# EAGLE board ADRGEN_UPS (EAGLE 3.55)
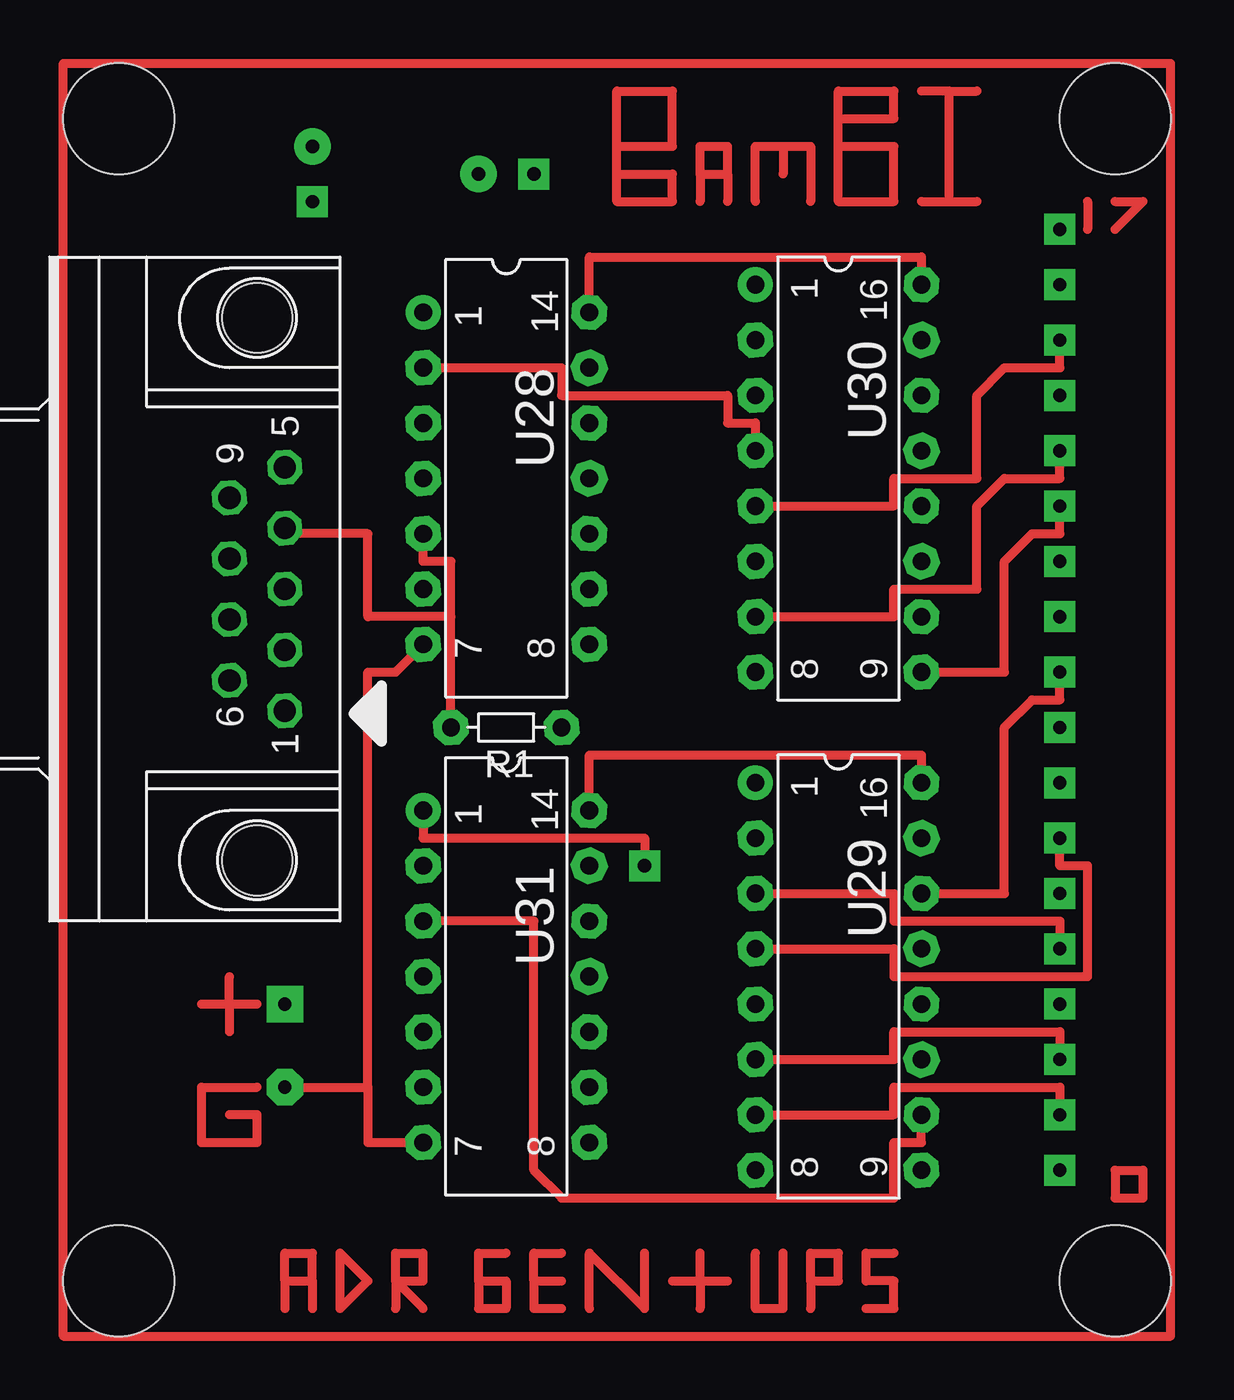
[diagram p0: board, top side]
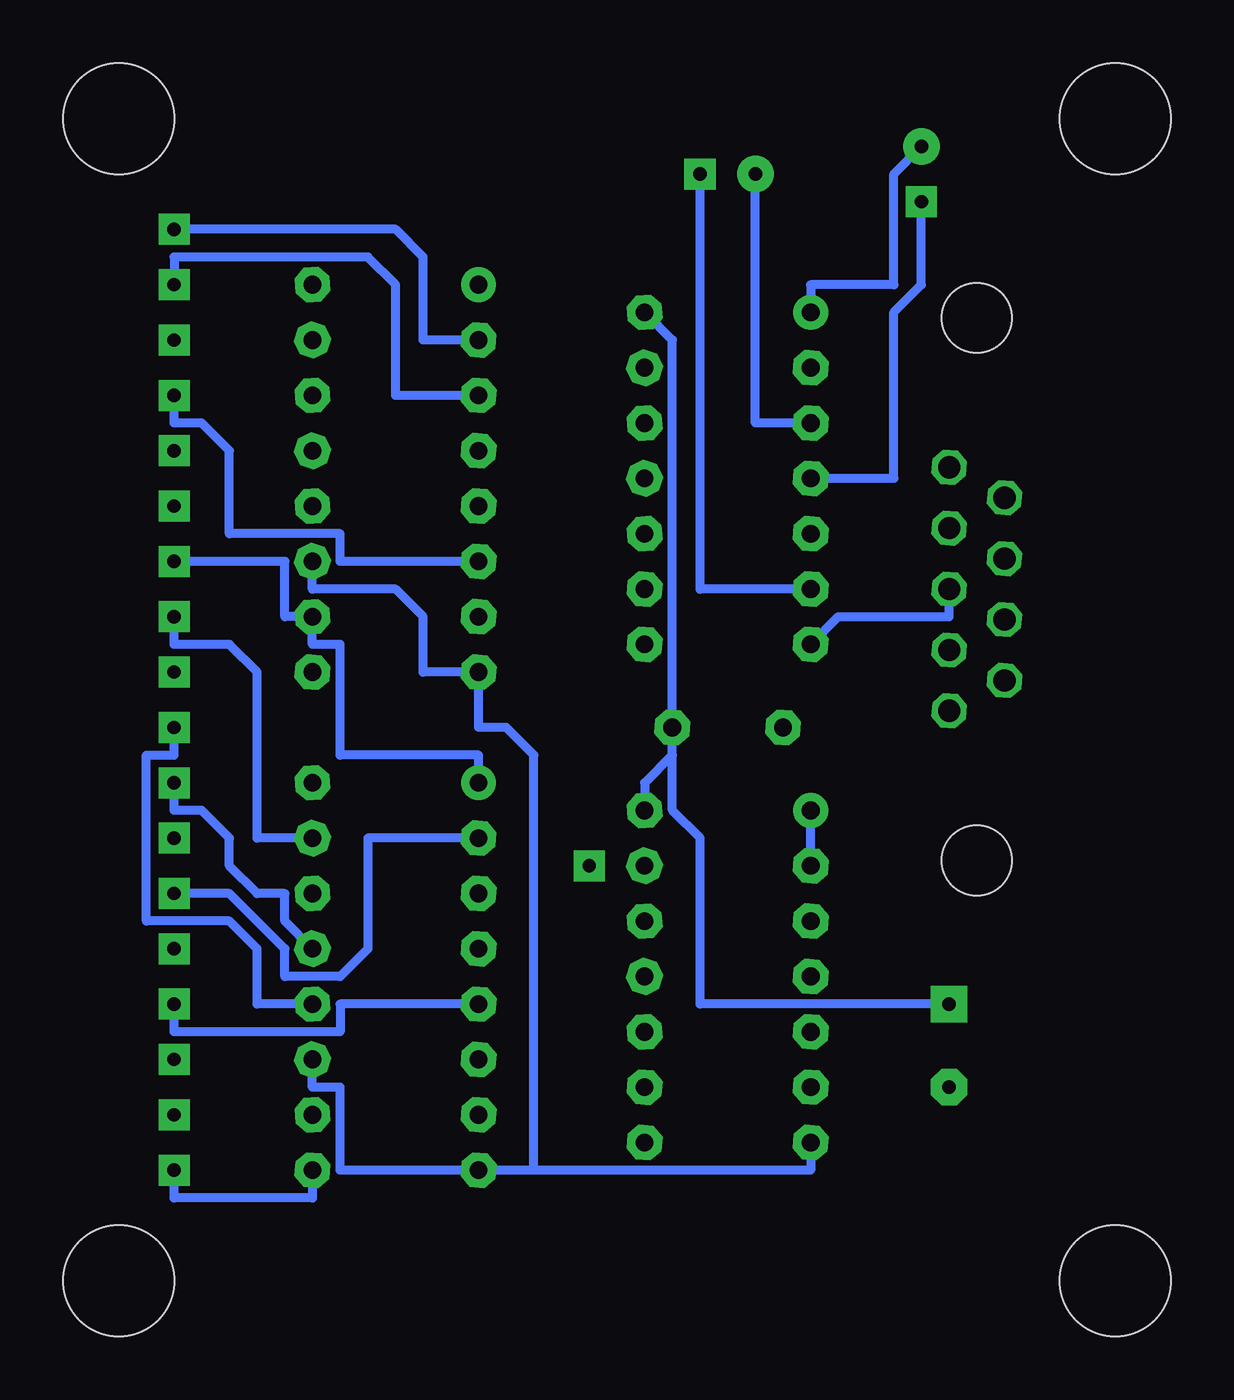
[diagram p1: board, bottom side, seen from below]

No outline drawn. Coordinates in mm, seen from the top.
Copper layers used: Top, Bottom
Holes 5.08 mm at 12.7,92.71 58.42,92.71 58.42,39.37 12.7,39.37

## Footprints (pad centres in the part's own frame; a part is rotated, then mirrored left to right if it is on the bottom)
09F/90 = drill 1.016 pad 1.575 octagon:  -5.588,-1.27;  -2.794,-1.27;  0,-1.27;  2.794,-1.27;  5.588,-1.27;  -4.191,1.27;  -1.397,1.27;  1.397,1.27;  4.191,1.27 | hole 3.2: 12.446,0; -12.446,0
5 = drill 0.813 pad 1.6 octagon:  -2.54,0;  2.54,0
L14 = drill 0.813 pad 1.6 round:  -7.62,-3.81 | drill 0.813 pad 1.6 octagon:  -5.08,-3.81;  -2.54,-3.81;  0,-3.81;  2.54,-3.81;  5.08,-3.81;  7.62,-3.81;  7.62,3.81;  5.08,3.81;  2.54,3.81;  0,3.81;  -2.54,3.81;  -5.08,3.81;  -7.62,3.81
L16 = drill 0.813 pad 1.6 round:  -8.89,-3.81 | drill 0.813 pad 1.6 octagon:  -6.35,-3.81;  -3.81,-3.81;  -1.27,-3.81;  1.27,-3.81;  3.81,-3.81;  6.35,-3.81;  8.89,-3.81;  8.89,3.81;  6.35,3.81;  3.81,3.81;  1.27,3.81;  -1.27,3.81;  -3.81,3.81;  -6.35,3.81;  -8.89,3.81

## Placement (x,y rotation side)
E$5  [09F/90]  19.05,71.12 90 top
R1  470ohms  [5]  30.48,64.77 180 top
U28  LS125A  [L14]  30.48,76.2 270 top
U29  74HC4040  [L16]  45.72,53.34 270 top
U30  74HC4040  [L16]  45.72,76.2 270 top
U31  74LS00  [L14]  30.48,53.34 270 top

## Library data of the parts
E$5 = connect
R1 = discrete
U28-U31 = 74xx

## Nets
S$1: U29.
S$2: U29.
S$3: U29.
S$4: U29.
S$5: U29.
S$6: U29.
S$7: U29.
S$8: U29.
S$9: U29.
S$10: U29.
S$11: U29.
S$12: U29. U30.
S$13: U30.
S$14: U30.
S$15: U30.
S$16: U30.
S$17: U30.
S$18: U30.
S$19: U31.
S$20: U29. U31.
S$21: U28. U30.
S$22: E$5. U28. U29. U30. U31.
S$23: U28.
S$24: R1. U28.
S$25: R1. U28. U29. U30. U31.
S$26: U28.
S$27: U28.
S$28: U28.

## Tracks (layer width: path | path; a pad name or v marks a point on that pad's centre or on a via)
S$1  (via drill 0.61 pad 1.42)
  Bottom 0.406: 49.53,44.45 49.53,43.18 55.88,43.18 v55.88,44.45
S$2  (via drill 0.61 pad 1.42)
  Top 0.406: 41.91,46.99 48.26,46.99 48.26,48.26 55.88,48.26 v55.88,46.99
S$3  (via drill 0.61 pad 1.42)
  Top 0.406: 41.91,49.53 48.26,49.53 48.26,50.8 55.88,50.8 v55.88,49.53
S$4  (via drill 0.61 pad 1.42)
  Bottom 0.406: 41.91,52.07 48.26,52.07 48.26,50.8 55.88,50.8 v55.88,52.07
S$5  (via drill 0.61 pad 1.42)
  Top 0.406: 41.91,57.15 48.26,57.15 48.26,55.88 55.88,55.88 v55.88,54.61
S$6  (via drill 0.61 pad 1.42)
  Bottom 0.406: 41.91,59.69 46.99,59.69 46.99,54.61 48.26,53.34 50.8,53.34 50.8,54.61 53.34,57.15 v55.88,57.15
S$7  (via drill 0.61 pad 1.42)
  Top 0.406: 41.91,54.61 48.26,54.61 48.26,53.34 57.15,53.34 57.15,58.42 55.88,58.42 v55.88,59.69
S$8  (via drill 0.61 pad 1.42)
  Bottom 0.406: 49.53,54.61 50.8,55.88 50.8,57.15 52.07,57.15 53.34,58.42 53.34,59.69 54.61,60.96 55.88,60.96 v55.88,62.23
S$9  (via drill 0.61 pad 1.42)
  Bottom 0.406: 49.53,52.07 52.07,52.07 52.07,54.61 53.34,55.88 57.15,55.88 57.15,63.5 55.88,63.5 v55.88,64.77
S$10  (via drill 0.61 pad 1.42)
  Top 0.406: 49.53,57.15 53.34,57.15 53.34,64.77 54.61,66.04 55.88,66.04 v55.88,67.31
S$11  (via drill 0.61 pad 1.42)
  Bottom 0.406: 49.53,59.69 52.07,59.69 52.07,67.31 53.34,68.58 55.88,68.58 v55.88,69.85
S$12  (via drill 0.61 pad 1.42)
  Bottom 0.406: 41.91,62.23 41.91,63.5 48.26,63.5 48.26,68.58 49.53,68.58 49.53,69.85 50.8,69.85 50.8,72.39 v55.88,72.39
S$13  (via drill 0.61 pad 1.42)
  Top 0.406: 49.53,67.31 53.34,67.31 53.34,72.39 54.61,73.66 55.88,73.66 v55.88,74.93
S$14  (via drill 0.61 pad 1.42)
  Top 0.406: 41.91,69.85 48.26,69.85 48.26,71.12 52.07,71.12 52.07,74.93 53.34,76.2 55.88,76.2 v55.88,77.47
S$15  (via drill 0.61 pad 1.42)
  Bottom 0.406: 41.91,72.39 48.26,72.39 48.26,73.66 53.34,73.66 53.34,77.47 54.61,78.74 55.88,78.74 v55.88,80.01
S$16  (via drill 0.61 pad 1.42)
  Top 0.406: 41.91,74.93 48.26,74.93 48.26,76.2 52.07,76.2 52.07,80.01 53.34,81.28 55.88,81.28 v55.88,82.55
S$17  (via drill 0.61 pad 1.42)
  Bottom 0.406: 41.91,80.01 45.72,80.01 45.72,85.09 46.99,86.36 55.88,86.36 v55.88,85.09
S$18  (via drill 0.61 pad 1.42)
  Bottom 0.406: 41.91,82.55 44.45,82.55 44.45,86.36 45.72,87.63 v55.88,87.63
S$19  (via drill 0.61 pad 1.42)
  Top 0.406: v36.83,58.42 36.83,59.69 26.67,59.69 26.67,60.96
  Bottom 0.406: 26.67,58.42 26.67,60.96
S$20
  Top 0.406: 26.67,55.88 31.75,55.88 31.75,44.45 33.02,43.18 48.26,43.18 48.26,45.72 49.53,45.72 49.53,46.99
S$21
  Top 0.406: 26.67,81.28 33.02,81.28 33.02,80.01 40.64,80.01 40.64,78.74 41.91,78.74 41.91,77.47
S$22  (via drill 0.61 pad 1.68)
  Top 0.406: 26.67,68.58 25.4,67.31 24.13,67.31 24.13,48.26 | 26.67,45.72 24.13,45.72 24.13,48.26 | v20.32,48.26 24.13,48.26
  Bottom 0.406: 49.53,72.39 49.53,71.12 45.72,71.12 44.45,69.85 44.45,67.31 41.91,67.31 41.91,64.77 40.64,64.77 39.37,63.5 39.37,44.45 | 49.53,49.53 49.53,48.26 48.26,48.26 48.26,44.45 41.91,44.45 39.37,44.45 | 20.32,71.12 20.32,69.85 25.4,69.85 26.67,68.58 | 39.37,44.45 26.67,44.45 26.67,45.72
S$23  (via drill 0.61 pad 1.68)
  Bottom 0.406: 26.67,78.74 29.21,78.74 v29.21,90.17
S$24
  Top 0.406: 26.67,73.66 26.67,72.39 27.94,72.39 27.94,69.85 | R1. 27.94,69.85 | 20.32,73.66 24.13,73.66 24.13,69.85 27.94,69.85
S$25  (via drill 0.61 pad 1.68)
  Top 0.406: U29. 49.53,63.5 34.29,63.5 U31. | U30. 49.53,86.36 34.29,86.36 U28.
  Bottom 0.406: U31. 34.29,62.23 33.02,63.5 | 33.02,63.5 33.02,64.77 33.02,82.55 U28. | v20.32,52.07 31.75,52.07 31.75,59.69 33.02,60.96 33.02,63.5
S$26  (via drill 0.61 pad 1.42)
  Bottom 0.406: 26.67,71.12 31.75,71.12 v31.75,90.17
S$27  (via drill 0.61 pad 1.68)
  Bottom 0.406: 26.67,83.82 26.67,85.09 22.86,85.09 22.86,90.17 v21.59,91.44
S$28  (via drill 0.61 pad 1.42)
  Bottom 0.406: 26.67,76.2 22.86,76.2 22.86,83.82 21.59,85.09 v21.59,88.9
S$29
  Top 0.406: 58.42,44.45 58.42,43.18 59.69,43.18 59.69,44.45 58.42,44.45
S$30
  Top 0.406: 17.78,52.07 17.78,53.34 | 17.78,52.07 17.78,50.8 | 17.78,52.07 19.05,52.07 | 16.51,52.07 17.78,52.07
S$31
  Top 0.406: 19.05,48.26 16.51,48.26 16.51,45.72 19.05,45.72 19.05,46.99 17.78,46.99
S$32
  Top 0.406: 10.16,36.83 10.16,95.25 60.96,95.25 60.96,36.83 10.16,36.83
S$33
  Top 0.406: 20.32,39.37 20.32,38.1 | 20.32,39.37 20.32,40.64 21.59,40.64 21.59,39.37 | 21.59,39.37 21.59,38.1 | 20.32,39.37 21.59,39.37
S$34
  Top 0.406: 22.86,38.1 22.86,40.64 24.13,39.37 22.86,38.1
S$35
  Top 0.406: 25.4,39.37 25.4,38.1 | 25.4,39.37 25.4,40.64 26.67,40.64 26.67,39.37 25.4,39.37 | 26.67,38.1 25.4,39.37
S$36
  Top 0.406: 30.48,40.64 29.21,40.64 29.21,39.37 | 29.21,39.37 29.21,38.1 30.48,38.1 30.48,39.37 29.21,39.37
S$37
  Top 0.406: 33.02,38.1 31.75,38.1 31.75,39.37 | 31.75,39.37 33.02,39.37 | 31.75,39.37 31.75,40.64 33.02,40.64
S$38
  Top 0.406: 34.29,38.1 34.29,40.64 36.83,38.1 36.83,40.64
S$39
  Top 0.406: 35.56,90.17 35.56,88.9 38.1,88.9 38.1,90.17 35.56,90.17 | 35.56,91.44 35.56,93.98 38.1,93.98 38.1,91.44 35.56,91.44 | 35.56,90.17 35.56,91.44
S$40
  Top 0.406: 39.37,90.17 39.37,88.9 | 39.37,90.17 39.37,91.44 40.64,91.44 40.64,90.17 | 40.64,90.17 40.64,88.9 | 39.37,90.17 40.64,90.17
S$41
  Top 0.406: 41.91,88.9 41.91,91.44 43.18,91.44 | 43.18,91.44 43.18,90.17 | 43.18,91.44 44.45,91.44 44.45,88.9
S$42
  Top 0.406: 45.72,91.44 45.72,88.9 48.26,88.9 48.26,91.44 45.72,91.44 | 45.72,92.71 45.72,93.98 48.26,93.98 48.26,92.71 45.72,92.71 | 45.72,91.44 45.72,92.71
S$43
  Top 0.406: 50.8,93.98 49.53,93.98 | 50.8,93.98 52.07,93.98 | 50.8,88.9 50.8,93.98 | 49.53,88.9 50.8,88.9 | 50.8,88.9 52.07,88.9
S$44
  Top 0.406: 39.37,39.37 39.37,40.64 | 39.37,39.37 39.37,38.1 | 39.37,39.37 40.64,39.37 | 38.1,39.37 39.37,39.37
S$45
  Top 0.406: 41.91,40.64 41.91,38.1 43.18,38.1 43.18,40.64
S$46
  Top 0.406: 44.45,39.37 44.45,38.1 | 44.45,39.37 44.45,40.64 45.72,40.64 45.72,39.37 44.45,39.37
S$47
  Top 0.406: 48.26,40.64 46.99,40.64 46.99,39.37 48.26,39.37 48.26,38.1 46.99,38.1
S$48
  Top 0.406: 57.15,88.9 57.15,87.63
S$49
  Top 0.406: 58.42,88.9 59.69,88.9 58.42,87.63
